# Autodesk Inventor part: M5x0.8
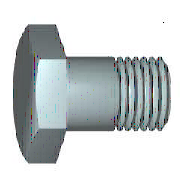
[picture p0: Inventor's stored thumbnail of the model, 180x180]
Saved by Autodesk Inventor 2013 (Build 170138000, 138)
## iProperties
IsCustomPart: 1
Created: 2009-02
Part Number: M5x0.8
Material: 강, 연강
Description: 6각 머리 볼트 및 6각 머리 나사
Document SubType Name: Modeling
Standard: KS B 1002
Designer: 한국산업디자인학원
Standards Organization: KS
Language: ko-KR
Size Designation: A  M 5 x 25
Categories: <MemberInstance><Categories><Category DisplayName="조임쇠" InternalName="e4da775c-781d-43d5-af7c-5136215cf5a6" Mnemonic="FSTN"><Category DisplayName="볼트" InternalN
Density: 1 g/cm^3
Author: 한국산업디자인학원
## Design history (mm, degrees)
sketch "스케치1"
  geometry: L1 (0, 2.5)-(0, 2.5); L2 (1, 2.5)-(12, 2.5); L3 (12, 2.5)-(12, 0); L4 (12, 0)-(-0.5, 0); L5 (-3, 0)-(14.5, 0) reference; L6 (-0.5, 0)-(-0.5, 2.5); L7 (-0.5, 2.5)-(0, 2.5); L8 (1, 2.5)-(0.509, 2.5); L9 (0.509, 2.5)-(0, 2.5); L10 (0, -0.5)-(0, 3) reference
  constraints: 16 end point, 3 collinear, 2 perpendicular
  dimensions: "d0" = 12 distance between parallel lines of L3 L1; "d1" = 11 distance from line of L2.start L3; "d2" = 5 diameter of L2 L4 (= GD); "d9" = 0.5001 distance between parallel lines of L6 L1 (computed from SD); "d10" = 5 diameter of L7 L4 (= d2); "d13" = 0.49086 distance of L2.start L8.end (computed from GAL); "d14" = 5 diameter of L9 L4 (= BDM)
revolve "본체" sketch "스케치1" stored, may be unused: angle "d12" = 90 deg
sketch "스케치2"
  geometry: L1 (0, 4.619)-(4, 2.309); L2 (4, 2.309)-(4, -2.309); L3 (4, -2.309)-(0, -4.619); L4 (0, -4.619)-(-4, -2.309); L5 (-4, -2.309)-(-4, 2.309); L6 (-4, 2.309)-(0, 4.619); 2 further points
  constraints: 12 end point, 1 coincident, 1 vertical, 11 other
  dimensions: "d11" = 8 distance between parallel lines of L5 L2 (= SW)
extrude "머리" join sketch "스케치2" distance "d3" = 3 (= KOH - SD); taper "d4" = 0 deg
sketch "스케치4"
  geometry: L1 (-3.5, 4)-(-3.5, 4.619); L2 (-3.5, 4.619)-(-3.143, 4.619); L3 (-3.143, 4.619)-(-3.5, 4); L4 (-4.1, 0)-(0.1, 0) reference; L5 (-0.5, 4.619)-(-3.5, 4.619) reference; L6 (-3.5, 2.309)-(-3.5, 4.619) reference
  constraints: 6 end point, 2 collinear, 1 perpendicular, 1 vertical
  dimensions: "d5" = 30 deg angle of L3 L1 (= ANG1); "d19" = 8 diameter of L1.start L4 (= SW0)
revolve "모따기1" sketch "스케치4" stored, may be unused: angle "d21" = 90 deg
workplane "Work Plane1"
body "Solid1"
feature "스레드" dims "d15" = 12, "d16" = 0
chamfer "모따기2" distance "d6" = 0.49076 (= -0.5 x SPD + 0.5 x GD); stored, may be unused: second distance "d7" = 0.49086 (computed from GUL), angle "d55" = 45 deg
other parameters: "NLG" = 25 [user parameter], "GD" = 5 (= NND) [user parameter; used in 2 equation terms], "BDM" = 5 (= NND) [user parameter; used in 1 equation term], "KOH" = 3.5 [user parameter; used in 1 equation term], "GEL" = 16 [user parameter], "SW" = 8 [user parameter; used in 3 equation terms], "SW0" = 8 (= SW) [user parameter; used in 1 equation term], "SPD" = 4.01848 (= NND - 1.2269 x PTC) [user parameter; used in 1 equation term], "SD2" = 6.88 (= SDH) [user parameter], "SD" = 0.5 [user parameter; used in 2 equation terms], "ANG1" = 30 deg [user parameter; used in 1 equation term], "GAL" = 0.49076 (= 0.61345 x PTC) [user parameter; used in 1 equation term], "GUL" = 0.49076 (= 0.61345 x PTC) [user parameter; used in 1 equation term], "d8" = 0, "RR" = 0.2 [user parameter], "d58" = 0, "TPU" = 12.5 (computed from PTC) [user parameter], "GD1" = 4.01848 (= THREADDIA - 1.2269 x PTC) [user parameter], "THREADDIA" = 5 [user parameter; used in 1 equation term], "SDH" = 6.88 [user parameter; used in 1 equation term], "TOA" = 30 deg [user parameter], "PTC" = 0.8 [user parameter; used in 5 equation terms], "NND" = 5 [user parameter; used in 3 equation terms], "E0" = 9.24 (= 1.155 x SW) [user parameter]
